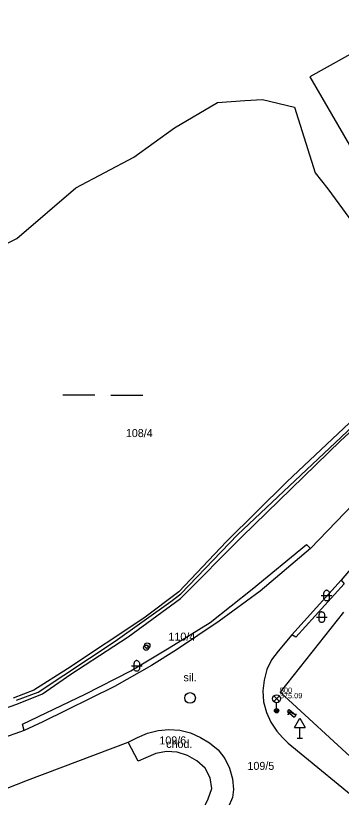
# Model space of a CAD drawing. Extents: x -836568 to -836015, y -1070547 to -1070212.
# Drawn here: x -836522 to -836491.5, y -1070322.1 to -1070248.8 of the extents above; entities that cross this region are included whole.
import ezdxf

# ---------------------------------------------------------------- set-up
doc = ezdxf.new("R2010")
doc.units = 0
for name, color, linetype in [('BodPole_mer', 7, 'Continuous'), ('BodPole_popis', 7, 'Continuous'), ('Doprava_body', 7, 'Continuous'), ('Doprava_hranice', 7, 'Continuous'), ('Doprava_kody', 7, 'Continuous'), ('OstPloch_hranice', 7, 'Continuous'), ('OstPloch_kody', 7, 'Continuous'), ('PovrZnIS_body', 7, 'Continuous'), ('PovrZnIS_hranice', 7, 'Continuous'), ('PovrZnIS_kody', 7, 'Continuous'), ('RuianPar_popis', 7, 'Continuous'), ('Stavby_linie', 7, 'Continuous'), ('Vodstvo_hranice', 7, 'Continuous'), ('Vodstvo_kody', 7, 'Continuous')]:
    doc.layers.add(name, color=color, linetype=linetype)

msp = doc.modelspace()

# ---------------------------------------------------------------- linework, layer by layer
at = {"layer": 'BodPole_mer'}
for p, q in [((-836493.93, -1070263.56), (-836493.93, -1070263.56)), ((-836492.75, -1070265.06), (-836492.75, -1070265.06)), ((-836491.56, -1070288.65), (-836491.56, -1070288.65)), ((-836496.59, -1070292.51), (-836496.59, -1070292.51)), ((-836501.2, -1070297.48), (-836501.2, -1070297.48)), ((-836500.78, -1070297.61), (-836500.78, -1070297.61)), ((-836502.23, -1070298.08), (-836502.23, -1070298.08)), ((-836494.75, -1070298.38), (-836494.75, -1070298.38)), ((-836494.37, -1070298.76), (-836494.37, -1070298.76)), ((-836491.51, -1070301.7), (-836491.51, -1070301.7)), ((-836499.84, -1070302.57), (-836499.84, -1070302.57)), ((-836499.1, -1070302.73), (-836499.1, -1070302.73)), ((-836506.71, -1070302.82), (-836506.71, -1070302.82)), ((-836506.56, -1070303.42), (-836506.56, -1070303.42)), ((-836506.51, -1070302.98), (-836506.51, -1070302.98)), ((-836507.45, -1070303.71), (-836507.45, -1070303.71)), ((-836509.99, -1070305.26), (-836509.99, -1070305.26)), ((-836503.78, -1070305.69), (-836503.78, -1070305.69)), ((-836502.92, -1070305.55), (-836502.92, -1070305.55)), ((-836511.44, -1070307.01), (-836511.44, -1070307.01)), ((-836496.11, -1070306.84), (-836496.11, -1070306.84)), ((-836495.74, -1070307.06), (-836495.74, -1070307.06)), ((-836512.67, -1070307.44), (-836512.67, -1070307.44)), ((-836509.67, -1070307.84), (-836509.67, -1070307.84)), ((-836509.77, -1070308.04), (-836509.77, -1070308.04)), ((-836507.6, -1070308.04), (-836507.6, -1070308.04)), ((-836506.93, -1070308.25), (-836506.93, -1070308.25)), ((-836497.41, -1070308.37), (-836497.41, -1070308.37)), ((-836498.02, -1070309.18), (-836498.02, -1070309.18)), ((-836517.14, -1070310.02), (-836517.14, -1070310.02)), ((-836509.27, -1070309.72), (-836509.27, -1070309.72)), ((-836498.47, -1070310.1), (-836498.47, -1070310.1)), ((-836516.81, -1070310.51), (-836516.81, -1070310.51)), ((-836511.22, -1070310.22), (-836511.22, -1070310.22)), ((-836498.73, -1070311.08), (-836498.73, -1070311.08)), ((-836520.29, -1070312.03), (-836520.29, -1070312.03)), ((-836519.9, -1070312.2), (-836519.9, -1070312.2)), ((-836512.75, -1070311.69), (-836512.75, -1070311.69)), ((-836498.85, -1070312.07), (-836498.85, -1070312.07)), ((-836497.25, -1070312.28), (-836497.25, -1070312.28)), ((-836497.22, -1070312.21), (-836497.22, -1070312.21)), ((-836521.92, -1070312.95), (-836521.92, -1070312.95)), ((-836519.48, -1070312.36), (-836519.48, -1070312.36)), ((-836515.49, -1070312.4), (-836515.49, -1070312.4)), ((-836505.66, -1070312.75), (-836505.66, -1070312.75)), ((-836521.89, -1070313.32), (-836521.89, -1070313.32)), ((-836498.78, -1070313.12), (-836498.78, -1070313.12)), ((-836498.51, -1070314.1), (-836498.51, -1070314.1)), ((-836497.55, -1070313.95), (-836497.55, -1070313.95)), ((-836496.53, -1070314.02), (-836496.53, -1070314.02)), ((-836496.37, -1070313.83), (-836496.37, -1070313.83)), ((-836495.76, -1070314.36), (-836495.76, -1070314.36)), ((-836521.34, -1070315.21), (-836521.34, -1070315.21)), ((-836519.45, -1070314.99), (-836519.45, -1070314.99)), ((-836498.1, -1070315.03), (-836498.1, -1070315.03)), ((-836495.92, -1070314.55), (-836495.92, -1070314.55)), ((-836521.21, -1070315.81), (-836521.21, -1070315.81)), ((-836508.64, -1070315.79), (-836508.64, -1070315.79)), ((-836507.63, -1070315.7), (-836507.63, -1070315.7)), ((-836506.6, -1070315.77), (-836506.6, -1070315.77)), ((-836497.52, -1070315.85), (-836497.52, -1070315.85)), ((-836510.57, -1070316.45), (-836510.57, -1070316.45)), ((-836509.63, -1070316.04), (-836509.63, -1070316.04)), ((-836505.63, -1070316.02), (-836505.63, -1070316.02)), ((-836504.69, -1070316.45), (-836504.69, -1070316.45)), ((-836497.01, -1070316.45), (-836497.01, -1070316.45)), ((-836495.37, -1070316.51), (-836495.37, -1070316.51)), ((-836511.44, -1070316.88), (-836511.44, -1070316.88)), ((-836503.83, -1070316.95), (-836503.83, -1070316.95)), ((-836496.48, -1070317), (-836496.48, -1070317)), ((-836508.87, -1070317.96), (-836508.87, -1070317.96)), ((-836507.86, -1070317.76), (-836507.86, -1070317.76)), ((-836506.85, -1070317.82), (-836506.85, -1070317.82)), ((-836505.89, -1070318.14), (-836505.89, -1070318.14)), ((-836503.04, -1070317.62), (-836503.04, -1070317.62)), ((-836510.52, -1070318.68), (-836510.52, -1070318.68)), ((-836509.8, -1070318.36), (-836509.8, -1070318.36)), ((-836505.01, -1070318.63), (-836505.01, -1070318.63)), ((-836502.41, -1070318.42), (-836502.41, -1070318.42)), ((-836504.25, -1070319.33), (-836504.25, -1070319.33)), ((-836501.96, -1070319.33), (-836501.96, -1070319.33)), ((-836503.78, -1070320.23), (-836503.78, -1070320.23)), ((-836501.67, -1070320.32), (-836501.67, -1070320.32)), ((-836520.89, -1070320.45), (-836520.89, -1070320.45)), ((-836503.63, -1070321.24), (-836503.63, -1070321.24)), ((-836501.58, -1070321.32), (-836501.58, -1070321.32))]:
    msp.add_line(p, q, dxfattribs=at)
at = {"layer": 'Doprava_body'}
for p, q in [((-836495.87, -1070315.51), (-836495.389, -1070314.656)), ((-836495.389, -1070314.656), (-836494.87, -1070315.51)), ((-836495.87, -1070315.51), (-836494.87, -1070315.51)), ((-836495.37, -1070316.51), (-836495.37, -1070315.51)), ((-836495.62, -1070316.51), (-836495.12, -1070316.51))]:
    msp.add_line(p, q, dxfattribs=at)
at = {"layer": 'Doprava_hranice'}
for points in [[(-836486.39, -1070290.44), (-836494.37, -1070298.76), (-836499.1, -1070302.73), (-836502.92, -1070305.55), (-836506.93, -1070308.25), (-836509.27, -1070309.72), (-836512.75, -1070311.69), (-836519.45, -1070314.99), (-836521.21, -1070315.81), (-836530.36, -1070319.04)], [(-836486.04, -1070295.25), (-836491.51, -1070301.7), (-836496.11, -1070306.84), (-836497.41, -1070308.37), (-836498.02, -1070309.18), (-836498.47, -1070310.1), (-836498.73, -1070311.08), (-836498.85, -1070312.07), (-836498.78, -1070313.12), (-836498.51, -1070314.1), (-836498.1, -1070315.03), (-836497.52, -1070315.85), (-836497.01, -1070316.45), (-836496.48, -1070317), (-836489.02, -1070323.12), (-836476.76, -1070333.19), (-836472.89, -1070336.35), (-836460.9, -1070346.19), (-836457.02, -1070349.36), (-836453.9, -1070351.88), (-836451.54, -1070353.74), (-836449.19, -1070355.59), (-836447.61, -1070356.83), (-836445.19, -1070358.65)], [(-836525.05, -1070322.08), (-836520.89, -1070320.45), (-836511.44, -1070316.88), (-836510.57, -1070316.45), (-836509.63, -1070316.04), (-836508.64, -1070315.79), (-836507.63, -1070315.7), (-836506.6, -1070315.77), (-836505.63, -1070316.02), (-836504.69, -1070316.45), (-836503.83, -1070316.95), (-836503.04, -1070317.62), (-836502.41, -1070318.42), (-836501.96, -1070319.33), (-836501.67, -1070320.32), (-836501.58, -1070321.32), (-836501.69, -1070322.09), (-836502.08, -1070323), (-836503.14, -1070325.25), (-836503.34, -1070325.71), (-836503.44, -1070326.18), (-836504.04, -1070330.63), (-836504.64, -1070331.81)], [(-836503.14, -1070325.25), (-836504.98, -1070324.39), (-836503.95, -1070322.21), (-836503.63, -1070321.24), (-836503.78, -1070320.23), (-836504.25, -1070319.33), (-836505.01, -1070318.63), (-836505.89, -1070318.14), (-836506.85, -1070317.82), (-836507.86, -1070317.76), (-836508.87, -1070317.96), (-836509.8, -1070318.36), (-836510.52, -1070318.68), (-836511.44, -1070316.88)]]:
    msp.add_lwpolyline(points, dxfattribs=at)
at = {"layer": 'OstPloch_hranice'}
for points in [[(-836521.21, -1070315.81), (-836521.34, -1070315.21), (-836515.49, -1070312.4), (-836511.22, -1070310.22), (-836507.6, -1070308.04), (-836503.78, -1070305.69), (-836499.84, -1070302.57), (-836494.75, -1070298.38), (-836494.37, -1070298.76)], [(-836491.51, -1070301.7), (-836491.21, -1070302.05), (-836495.74, -1070307.06), (-836496.11, -1070306.84)]]:
    msp.add_lwpolyline(points, dxfattribs=at)
at = {"layer": 'OstPloch_kody'}
for p, q in [((-836493.37, -1070303.16), (-836492.37, -1070303.16)), ((-836493.12, -1070303.41), (-836493.12, -1070302.91)), ((-836492.62, -1070302.91), (-836492.62, -1070303.41)), ((-836493.57, -1070305.43), (-836493.57, -1070304.93)), ((-836493.07, -1070304.93), (-836493.07, -1070305.43)), ((-836493.82, -1070305.18), (-836492.82, -1070305.18)), ((-836511.15, -1070309.75), (-836510.15, -1070309.75)), ((-836510.9, -1070310), (-836510.9, -1070309.5)), ((-836510.4, -1070309.5), (-836510.4, -1070310))]:
    msp.add_line(p, q, dxfattribs=at)
for points in [[(-836492.87, -1070302.66), (-836492.915, -1070302.664), (-836492.962, -1070302.678), (-836493.007, -1070302.701), (-836493.047, -1070302.733), (-836493.079, -1070302.773), (-836493.102, -1070302.818), (-836493.116, -1070302.865), (-836493.12, -1070302.91)], [(-836492.87, -1070302.66), (-836492.825, -1070302.664), (-836492.778, -1070302.678), (-836492.733, -1070302.701), (-836492.693, -1070302.733), (-836492.661, -1070302.773), (-836492.638, -1070302.818), (-836492.624, -1070302.865), (-836492.62, -1070302.91)], [(-836492.87, -1070303.66), (-836492.915, -1070303.656), (-836492.962, -1070303.642), (-836493.007, -1070303.619), (-836493.047, -1070303.587), (-836493.079, -1070303.547), (-836493.102, -1070303.502), (-836493.116, -1070303.455), (-836493.12, -1070303.41)], [(-836492.62, -1070303.41), (-836492.624, -1070303.455), (-836492.638, -1070303.502), (-836492.661, -1070303.547), (-836492.693, -1070303.587), (-836492.733, -1070303.619), (-836492.778, -1070303.642), (-836492.825, -1070303.656), (-836492.87, -1070303.66)], [(-836493.32, -1070304.68), (-836493.365, -1070304.684), (-836493.412, -1070304.698), (-836493.457, -1070304.721), (-836493.497, -1070304.753), (-836493.529, -1070304.793), (-836493.552, -1070304.838), (-836493.566, -1070304.885), (-836493.57, -1070304.93)], [(-836493.32, -1070304.68), (-836493.275, -1070304.684), (-836493.228, -1070304.698), (-836493.183, -1070304.721), (-836493.143, -1070304.753), (-836493.111, -1070304.793), (-836493.088, -1070304.838), (-836493.074, -1070304.885), (-836493.07, -1070304.93)], [(-836493.32, -1070305.68), (-836493.365, -1070305.676), (-836493.412, -1070305.662), (-836493.457, -1070305.639), (-836493.497, -1070305.607), (-836493.529, -1070305.567), (-836493.552, -1070305.522), (-836493.566, -1070305.475), (-836493.57, -1070305.43)], [(-836493.07, -1070305.43), (-836493.074, -1070305.475), (-836493.088, -1070305.522), (-836493.111, -1070305.567), (-836493.143, -1070305.607), (-836493.183, -1070305.639), (-836493.228, -1070305.662), (-836493.275, -1070305.676), (-836493.32, -1070305.68)], [(-836510.65, -1070309.25), (-836510.695, -1070309.254), (-836510.742, -1070309.268), (-836510.787, -1070309.291), (-836510.827, -1070309.323), (-836510.859, -1070309.363), (-836510.882, -1070309.408), (-836510.896, -1070309.455), (-836510.9, -1070309.5)], [(-836510.65, -1070309.25), (-836510.605, -1070309.254), (-836510.558, -1070309.268), (-836510.513, -1070309.291), (-836510.473, -1070309.323), (-836510.441, -1070309.363), (-836510.418, -1070309.408), (-836510.404, -1070309.455), (-836510.4, -1070309.5)], [(-836510.65, -1070310.25), (-836510.695, -1070310.246), (-836510.742, -1070310.232), (-836510.787, -1070310.209), (-836510.827, -1070310.177), (-836510.859, -1070310.137), (-836510.882, -1070310.092), (-836510.896, -1070310.045), (-836510.9, -1070310)], [(-836510.4, -1070310), (-836510.404, -1070310.045), (-836510.418, -1070310.092), (-836510.441, -1070310.137), (-836510.473, -1070310.177), (-836510.513, -1070310.209), (-836510.558, -1070310.232), (-836510.605, -1070310.246), (-836510.65, -1070310.25)]]:
    msp.add_lwpolyline(points, dxfattribs=at)
at = {"layer": 'PovrZnIS_body'}
for p, q in [((-836497.815, -1070313.09), (-836497.285, -1070312.56)), ((-836497.815, -1070312.56), (-836497.285, -1070313.09)), ((-836497.55, -1070313.75), (-836497.55, -1070313.2))]:
    msp.add_line(p, q, dxfattribs=at)
for centre, radius in [((-836509.77, -1070308.04), 0.25), ((-836509.67, -1070307.84), 0.25), ((-836505.66, -1070312.75), 0.5)]:
    msp.add_circle(centre, radius, dxfattribs=at)
for centre, major_axis in [((-836497.55, -1070312.825), (0.375, 0)), ((-836497.55, -1070313.95), (0.2, 0)), ((-836497.546, -1070313.95), (0.125, 0)), ((-836497.546, -1070313.95), (0.05, 0))]:
    msp.add_ellipse(centre, major_axis=major_axis, ratio=0.999998, dxfattribs=at)
at = {"layer": 'PovrZnIS_hranice'}
for p, q in [((-836496.53, -1070314.02), (-836496.37, -1070313.83)), ((-836496.53, -1070314.02), (-836495.92, -1070314.55)), ((-836496.37, -1070313.83), (-836495.76, -1070314.36)), ((-836495.76, -1070314.36), (-836495.92, -1070314.55))]:
    msp.add_line(p, q, dxfattribs=at)
at = {"layer": 'PovrZnIS_kody'}
for p, q in [((-836496.53, -1070314.27), (-836496.42, -1070314.27)), ((-836496.42, -1070314.27), (-836496.42, -1070314.02)), ((-836496.42, -1070314.02), (-836495.92, -1070314.27)), ((-836495.92, -1070314.27), (-836495.675, -1070314.27))]:
    msp.add_line(p, q, dxfattribs=at)
at = {"layer": 'RuianPar_popis'}
for p, q in [((-836511.67, -1070288.31), (-836511.67, -1070288.31)), ((-836507.68, -1070307.38), (-836507.68, -1070307.38)), ((-836508.53, -1070317.1), (-836508.53, -1070317.1)), ((-836500.28, -1070319.49), (-836500.28, -1070319.49))]:
    msp.add_line(p, q, dxfattribs=at)
at = {"layer": 'Stavby_linie'}
for points in [[(-836484.13, -1070248.82), (-836494.44, -1070254.55), (-836490.71, -1070260.96)], [(-836521.92, -1070312.95), (-836519.9, -1070312.2), (-836512.67, -1070307.44), (-836507.45, -1070303.71), (-836506.51, -1070302.98), (-836501.2, -1070297.48), (-836487.74, -1070284.74), (-836486.21, -1070283.75)], [(-836491.27, -1070304.7), (-836497.22, -1070312.21), (-836489.89, -1070318.94)]]:
    msp.add_lwpolyline(points, dxfattribs=at)
at = {"layer": 'Vodstvo_hranice'}
for points in [[(-836525.34, -1070271.43), (-836521.88, -1070269.71), (-836516.37, -1070264.96), (-836510.93, -1070262.08), (-836507.11, -1070259.33), (-836503.08, -1070256.96), (-836500.52, -1070256.76), (-836498.86, -1070256.68), (-836495.87, -1070257.41), (-836493.93, -1070263.56), (-836492.75, -1070265.06), (-836486.76, -1070273.24), (-836482.01, -1070279.63), (-836483.74, -1070282.01), (-836486.21, -1070283.75)], [(-836538.28, -1070299.17), (-836536.67, -1070302.12), (-836537.27, -1070302.49), (-836535.82, -1070305.08), (-836535.28, -1070304.8), (-836529.27, -1070315.73), (-836524.75, -1070314.46), (-836523.12, -1070313.78), (-836521.89, -1070313.32), (-836519.48, -1070312.36), (-836516.81, -1070310.51), (-836511.44, -1070307.01), (-836506.56, -1070303.42), (-836500.78, -1070297.61), (-836491.56, -1070288.65), (-836487.98, -1070285.34), (-836486.83, -1070284.4), (-836486.48, -1070284.32), (-836486.34, -1070284.49), (-836485.89, -1070284.09), (-836486.21, -1070283.75)], [(-836486.21, -1070283.75), (-836486.51, -1070283.72), (-836487.17, -1070283.89), (-836488.08, -1070284.48), (-836496.59, -1070292.51), (-836502.23, -1070298.08), (-836506.71, -1070302.82), (-836509.99, -1070305.26), (-836517.14, -1070310.02), (-836520.29, -1070312.03), (-836522.22, -1070312.76)]]:
    msp.add_lwpolyline(points, dxfattribs=at)
at = {"layer": 'Vodstvo_kody'}
for p, q in [((-836514.57, -1070284.39), (-836517.57, -1070284.39)), ((-836513.07, -1070284.39), (-836510.07, -1070284.39))]:
    msp.add_line(p, q, dxfattribs=at)

# ---------------------------------------------------------------- texts
at = {"layer": 'BodPole_popis'}
for s, p in [('375.09', (-836497.25, -1070312.78)), ('500', (-836497.25, -1070312.28))]:
    msp.add_text(s, height=0.5, dxfattribs=at).set_placement(p)
at = {"layer": 'Doprava_kody'}
for s, p in [('sil.', (-836506.27, -1070311.19)), ('chod.', (-836507.89, -1070317.43))]:
    msp.add_text(s, height=0.75, dxfattribs=at).set_placement(p)
at = {"layer": 'PovrZnIS_body'}
for p in [(-836509.841, -1070308.183), (-836509.741, -1070307.983)]:
    msp.add_text('V', height=0.25, dxfattribs=at).set_placement(p)
at = {"layer": 'RuianPar_popis'}
for s, p in [('108/4', (-836511.67, -1070288.31)), ('110/4', (-836507.68, -1070307.38)), ('109/6', (-836508.53, -1070317.1)), ('109/5', (-836500.28, -1070319.49))]:
    msp.add_text(s, height=0.75, dxfattribs=at).set_placement(p)

doc.saveas('drawing.dxf')
